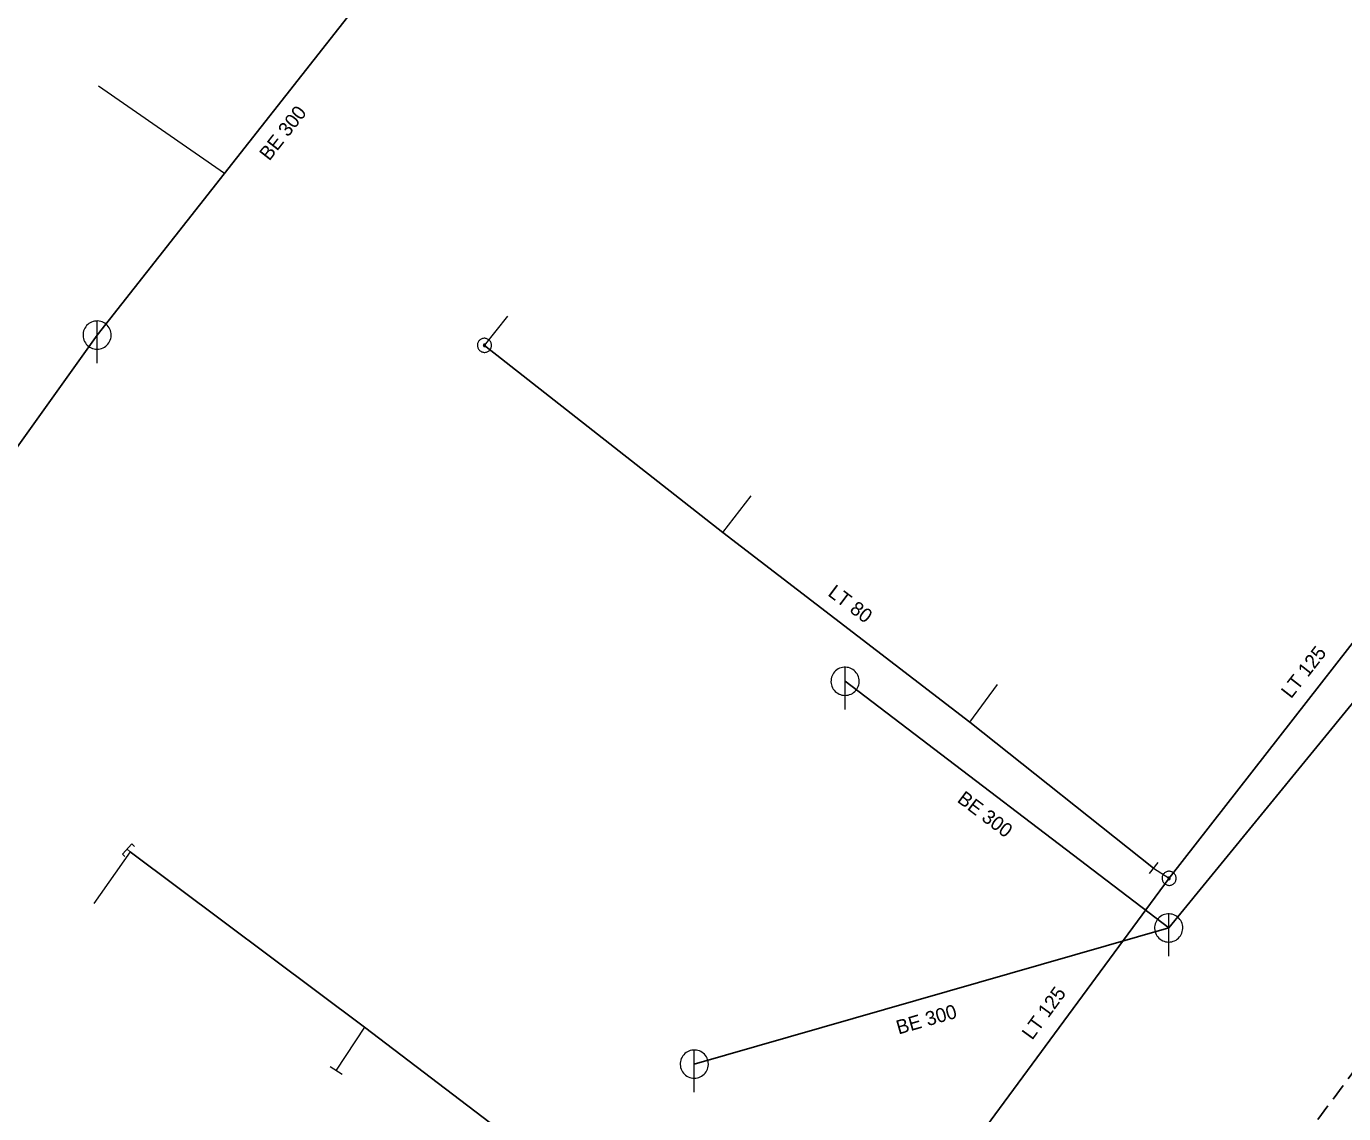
# Model space of a CAD drawing. Extents: x -791337 to -790755, y -988454 to -987923.
# Drawn here: x -790949.7 to -790856.3, y -988339.8 to -988262.8 of the extents above; entities that cross this region are included whole.
import ezdxf

# ---------------------------------------------------------------- set-up
doc = ezdxf.new("R2010")
doc.units = 0
doc.header["$LTSCALE"] = 0.4
doc.linetypes.add('MEDIUM_DASHED', pattern=[4.5, 3, -1.5])
for name, color, linetype, lineweight in [('1', 7, 'Continuous', 13), ('11', 7, 'Continuous', 13), ('13', 7, 'Continuous', 13), ('14', 7, 'Continuous', 25), ('17', 7, 'Continuous', 25), ('22', 7, 'Continuous', 13), ('34', 7, 'Continuous', 13), ('47', 7, 'Continuous', 13), ('63', 7, 'MEDIUM_DASHED', 25)]:
    doc.layers.add(name, color=color, linetype=linetype, lineweight=lineweight)

msp = doc.modelspace()

# ---------------------------------------------------------------- linework, layer by layer
at = {"layer": '11'}
msp.add_line((-790944.59, -988266.969), (-790935.659, -988273.171), dxfattribs=at)
at = {"layer": '13'}
for p, q in [((-790917.221, -988285.369), (-790915.555, -988283.298)), ((-790900.313, -988298.646), (-790898.305, -988296.026)), ((-790882.793, -988312.085), (-790880.839, -988309.421)), ((-790942.351, -988321.278), (-790944.916, -988324.931)), ((-790925.727, -988333.706), (-790927.739, -988336.76))]:
    msp.add_line(p, q, dxfattribs=at)
at = {"layer": '14'}
for p, q in [((-790944.69, -988284.64), (-790919.68, -988252.879)), ((-790902.342, -988336.322), (-790868.702, -988326.671))]:
    msp.add_line(p, q, dxfattribs=at)
at = {"layer": '14', "lineweight": 13}
msp.add_line((-790869.779, -988322.429), (-790868.671, -988323.153), dxfattribs=at)
at = {"layer": '14'}
for points in [[(-790967.359, -988315.936), (-790959.611, -988305.497), (-790944.69, -988284.64)], [(-790891.652, -988309.185), (-790868.702, -988326.671), (-790834.989, -988285.46)]]:
    msp.add_lwpolyline(points, dxfattribs=at)
at = {"layer": '17'}
for points in [[(-790868.671, -988323.153), (-790846.136, -988294.261), (-790834.335, -988278.502)], [(-790917.221, -988285.369), (-790900.313, -988298.646), (-790882.793, -988312.085), (-790869.779, -988322.429)], [(-790942.565, -988321.078), (-790942.351, -988321.278), (-790925.727, -988333.706), (-790908.984, -988346.43), (-790896.409, -988355.739)], [(-790894.383, -988357.266), (-790882.949, -988342.528), (-790868.671, -988323.153)]]:
    msp.add_lwpolyline(points, dxfattribs=at)
at = {"layer": '22'}
for p, q in [((-790944.69, -988286.64), (-790944.689, -988283.64)), ((-790891.652, -988311.185), (-790891.651, -988308.185)), ((-790868.702, -988328.671), (-790868.701, -988325.671)), ((-790902.343, -988338.323), (-790902.342, -988335.323))]:
    msp.add_line(p, q, dxfattribs=at)
for points in [[(-790943.69, -988284.64), (-790943.695, -988284.531), (-790943.713, -988284.423), (-790943.743, -988284.317), (-790943.783, -988284.216), (-790943.835, -988284.119), (-790943.897, -988284.029), (-790943.969, -988283.946), (-790944.049, -988283.872), (-790944.137, -988283.806), (-790944.231, -988283.751), (-790944.331, -988283.706), (-790944.436, -988283.673), (-790944.543, -988283.651), (-790944.652, -988283.641), (-790944.762, -988283.643), (-790944.87, -988283.657), (-790944.977, -988283.682), (-790945.08, -988283.719), (-790945.178, -988283.768), (-790945.27, -988283.826), (-790945.356, -988283.895), (-790945.433, -988283.972), (-790945.502, -988284.058), (-790945.561, -988284.15), (-790945.609, -988284.248), (-790945.646, -988284.351), (-790945.672, -988284.458), (-790945.686, -988284.566), (-790945.689, -988284.676), (-790945.679, -988284.785), (-790945.658, -988284.892), (-790945.624, -988284.996), (-790945.58, -988285.096), (-790945.525, -988285.191), (-790945.459, -988285.279), (-790945.385, -988285.359), (-790945.302, -988285.431), (-790945.212, -988285.493), (-790945.116, -988285.545), (-790945.014, -988285.586), (-790944.909, -988285.616), (-790944.801, -988285.634), (-790944.691, -988285.64), (-790944.582, -988285.634), (-790944.474, -988285.616), (-790944.369, -988285.587), (-790944.267, -988285.546), (-790944.17, -988285.494), (-790944.08, -988285.432), (-790943.997, -988285.361), (-790943.922, -988285.281), (-790943.857, -988285.193), (-790943.801, -988285.099), (-790943.757, -988284.999), (-790943.723, -988284.895), (-790943.701, -988284.787), (-790943.691, -988284.678)], [(-790890.652, -988309.185), (-790890.657, -988309.076), (-790890.675, -988308.968), (-790890.705, -988308.862), (-790890.745, -988308.761), (-790890.797, -988308.664), (-790890.859, -988308.574), (-790890.931, -988308.491), (-790891.011, -988308.417), (-790891.099, -988308.351), (-790891.193, -988308.296), (-790891.293, -988308.251), (-790891.398, -988308.218), (-790891.505, -988308.196), (-790891.614, -988308.186), (-790891.724, -988308.188), (-790891.832, -988308.202), (-790891.939, -988308.227), (-790892.042, -988308.264), (-790892.14, -988308.313), (-790892.232, -988308.371), (-790892.318, -988308.44), (-790892.395, -988308.517), (-790892.464, -988308.603), (-790892.523, -988308.695), (-790892.571, -988308.793), (-790892.608, -988308.896), (-790892.634, -988309.003), (-790892.648, -988309.111), (-790892.651, -988309.221), (-790892.641, -988309.33), (-790892.62, -988309.437), (-790892.586, -988309.541), (-790892.542, -988309.641), (-790892.487, -988309.736), (-790892.421, -988309.824), (-790892.347, -988309.904), (-790892.264, -988309.976), (-790892.174, -988310.038), (-790892.078, -988310.09), (-790891.976, -988310.131), (-790891.871, -988310.161), (-790891.763, -988310.179), (-790891.653, -988310.185), (-790891.544, -988310.179), (-790891.436, -988310.161), (-790891.331, -988310.132), (-790891.229, -988310.091), (-790891.132, -988310.039), (-790891.042, -988309.977), (-790890.959, -988309.906), (-790890.884, -988309.826), (-790890.819, -988309.738), (-790890.763, -988309.644), (-790890.719, -988309.544), (-790890.685, -988309.44), (-790890.663, -988309.332), (-790890.653, -988309.223)], [(-790867.702, -988326.671), (-790867.707, -988326.562), (-790867.725, -988326.454), (-790867.755, -988326.348), (-790867.795, -988326.247), (-790867.847, -988326.15), (-790867.909, -988326.06), (-790867.981, -988325.977), (-790868.061, -988325.903), (-790868.149, -988325.837), (-790868.243, -988325.782), (-790868.343, -988325.737), (-790868.448, -988325.704), (-790868.555, -988325.682), (-790868.664, -988325.672), (-790868.774, -988325.674), (-790868.882, -988325.688), (-790868.989, -988325.713), (-790869.092, -988325.75), (-790869.19, -988325.799), (-790869.282, -988325.857), (-790869.368, -988325.926), (-790869.445, -988326.003), (-790869.514, -988326.089), (-790869.573, -988326.181), (-790869.621, -988326.279), (-790869.658, -988326.382), (-790869.684, -988326.489), (-790869.698, -988326.597), (-790869.701, -988326.707), (-790869.691, -988326.816), (-790869.67, -988326.923), (-790869.636, -988327.027), (-790869.592, -988327.127), (-790869.537, -988327.222), (-790869.471, -988327.31), (-790869.397, -988327.39), (-790869.314, -988327.462), (-790869.224, -988327.524), (-790869.128, -988327.576), (-790869.026, -988327.617), (-790868.921, -988327.647), (-790868.813, -988327.665), (-790868.703, -988327.671), (-790868.594, -988327.665), (-790868.486, -988327.647), (-790868.381, -988327.618), (-790868.279, -988327.577), (-790868.182, -988327.525), (-790868.092, -988327.463), (-790868.009, -988327.392), (-790867.934, -988327.312), (-790867.869, -988327.224), (-790867.813, -988327.13), (-790867.769, -988327.03), (-790867.735, -988326.926), (-790867.713, -988326.818), (-790867.703, -988326.709)], [(-790901.343, -988336.323), (-790901.348, -988336.214), (-790901.366, -988336.106), (-790901.396, -988336), (-790901.436, -988335.899), (-790901.488, -988335.802), (-790901.55, -988335.712), (-790901.622, -988335.629), (-790901.702, -988335.555), (-790901.79, -988335.489), (-790901.884, -988335.434), (-790901.984, -988335.389), (-790902.089, -988335.356), (-790902.196, -988335.334), (-790902.305, -988335.324), (-790902.415, -988335.326), (-790902.523, -988335.34), (-790902.63, -988335.365), (-790902.733, -988335.402), (-790902.831, -988335.451), (-790902.923, -988335.509), (-790903.009, -988335.578), (-790903.086, -988335.655), (-790903.155, -988335.741), (-790903.214, -988335.833), (-790903.262, -988335.931), (-790903.299, -988336.034), (-790903.325, -988336.141), (-790903.339, -988336.249), (-790903.342, -988336.359), (-790903.332, -988336.468), (-790903.311, -988336.575), (-790903.277, -988336.679), (-790903.233, -988336.779), (-790903.178, -988336.874), (-790903.112, -988336.962), (-790903.038, -988337.042), (-790902.955, -988337.114), (-790902.865, -988337.176), (-790902.769, -988337.228), (-790902.667, -988337.269), (-790902.562, -988337.299), (-790902.454, -988337.317), (-790902.344, -988337.323), (-790902.235, -988337.317), (-790902.127, -988337.299), (-790902.022, -988337.27), (-790901.92, -988337.229), (-790901.823, -988337.177), (-790901.733, -988337.115), (-790901.65, -988337.044), (-790901.575, -988336.964), (-790901.51, -988336.876), (-790901.454, -988336.782), (-790901.41, -988336.682), (-790901.376, -988336.578), (-790901.354, -988336.47), (-790901.344, -988336.361)]]:
    msp.add_lwpolyline(points, close=True, dxfattribs=at)
at = {"layer": '34'}
for p, q in [((-790869.467, -988322.037), (-790870.09, -988322.819)), ((-790928.156, -988336.485), (-790927.321, -988337.035))]:
    msp.add_line(p, q, dxfattribs=at)
at = {"layer": '47'}
for points in [[(-790916.827, -988285.677), (-790916.797, -988285.635), (-790916.772, -988285.589), (-790916.752, -988285.541), (-790916.736, -988285.491), (-790916.726, -988285.439), (-790916.721, -988285.387), (-790916.722, -988285.335), (-790916.729, -988285.283), (-790916.74, -988285.232), (-790916.756, -988285.182), (-790916.779, -988285.134), (-790916.806, -988285.09), (-790916.837, -988285.048), (-790916.873, -988285.01), (-790916.912, -988284.975), (-790916.954, -988284.945), (-790917, -988284.92), (-790917.049, -988284.899), (-790917.098, -988284.884), (-790917.15, -988284.874), (-790917.202, -988284.869), (-790917.255, -988284.87), (-790917.307, -988284.876), (-790917.357, -988284.887), (-790917.407, -988284.904), (-790917.455, -988284.927), (-790917.5, -988284.953), (-790917.541, -988284.985), (-790917.579, -988285.021), (-790917.614, -988285.06), (-790917.644, -988285.102), (-790917.669, -988285.148), (-790917.691, -988285.196), (-790917.705, -988285.246), (-790917.715, -988285.298), (-790917.721, -988285.35), (-790917.72, -988285.402), (-790917.714, -988285.454), (-790917.702, -988285.505), (-790917.685, -988285.555), (-790917.662, -988285.603), (-790917.636, -988285.647), (-790917.604, -988285.689), (-790917.568, -988285.727), (-790917.529, -988285.762), (-790917.487, -988285.792), (-790917.441, -988285.817), (-790917.393, -988285.838), (-790917.343, -988285.853), (-790917.291, -988285.863), (-790917.239, -988285.869), (-790917.188, -988285.867), (-790917.136, -988285.861), (-790917.084, -988285.849), (-790917.034, -988285.833), (-790916.986, -988285.81), (-790916.943, -988285.784), (-790916.9, -988285.752), (-790916.862, -988285.716)], [(-790917.156, -988285.419), (-790917.15, -988285.412), (-790917.147, -988285.405), (-790917.144, -988285.397), (-790917.141, -988285.389), (-790917.139, -988285.38), (-790917.139, -988285.372), (-790917.139, -988285.363), (-790917.14, -988285.354), (-790917.142, -988285.346), (-790917.144, -988285.338), (-790917.148, -988285.33), (-790917.153, -988285.323), (-790917.158, -988285.316), (-790917.163, -988285.31), (-790917.17, -988285.304), (-790917.177, -988285.298), (-790917.184, -988285.295), (-790917.192, -988285.292), (-790917.2, -988285.289), (-790917.209, -988285.287), (-790917.217, -988285.287), (-790917.226, -988285.287), (-790917.235, -988285.288), (-790917.244, -988285.289), (-790917.251, -988285.292), (-790917.259, -988285.296), (-790917.266, -988285.301), (-790917.273, -988285.306), (-790917.279, -988285.311), (-790917.285, -988285.318), (-790917.291, -988285.325), (-790917.294, -988285.332), (-790917.297, -988285.34), (-790917.3, -988285.348), (-790917.302, -988285.357), (-790917.303, -988285.365), (-790917.302, -988285.374), (-790917.301, -988285.383), (-790917.3, -988285.392), (-790917.297, -988285.399), (-790917.293, -988285.407), (-790917.288, -988285.414), (-790917.283, -988285.421), (-790917.278, -988285.427), (-790917.271, -988285.433), (-790917.264, -988285.439), (-790917.257, -988285.442), (-790917.249, -988285.445), (-790917.241, -988285.448), (-790917.232, -988285.45), (-790917.224, -988285.451), (-790917.215, -988285.45), (-790917.206, -988285.449), (-790917.198, -988285.447), (-790917.19, -988285.445), (-790917.182, -988285.441), (-790917.175, -988285.436), (-790917.168, -988285.431), (-790917.162, -988285.426)], [(-790868.362, -988322.759), (-790868.405, -988322.729), (-790868.451, -988322.703), (-790868.499, -988322.684), (-790868.548, -988322.668), (-790868.6, -988322.657), (-790868.653, -988322.653), (-790868.704, -988322.654), (-790868.756, -988322.661), (-790868.807, -988322.672), (-790868.857, -988322.689), (-790868.905, -988322.711), (-790868.949, -988322.738), (-790868.991, -988322.769), (-790869.03, -988322.805), (-790869.064, -988322.844), (-790869.094, -988322.887), (-790869.12, -988322.933), (-790869.14, -988322.981), (-790869.155, -988323.03), (-790869.166, -988323.082), (-790869.17, -988323.135), (-790869.169, -988323.187), (-790869.163, -988323.239), (-790869.152, -988323.29), (-790869.134, -988323.339), (-790869.112, -988323.387), (-790869.085, -988323.432), (-790869.054, -988323.473), (-790869.018, -988323.512), (-790868.979, -988323.546), (-790868.936, -988323.576), (-790868.89, -988323.602), (-790868.842, -988323.623), (-790868.793, -988323.637), (-790868.741, -988323.648), (-790868.689, -988323.653), (-790868.636, -988323.652), (-790868.584, -988323.646), (-790868.533, -988323.634), (-790868.484, -988323.616), (-790868.436, -988323.594), (-790868.391, -988323.568), (-790868.35, -988323.536), (-790868.311, -988323.5), (-790868.277, -988323.461), (-790868.247, -988323.418), (-790868.221, -988323.372), (-790868.201, -988323.325), (-790868.186, -988323.275), (-790868.175, -988323.223), (-790868.17, -988323.171), (-790868.172, -988323.119), (-790868.178, -988323.067), (-790868.19, -988323.016), (-790868.207, -988322.966), (-790868.229, -988322.918), (-790868.255, -988322.874), (-790868.287, -988322.832), (-790868.323, -988322.793)], [(-790868.62, -988323.088), (-790868.627, -988323.082), (-790868.635, -988323.079), (-790868.642, -988323.076), (-790868.65, -988323.073), (-790868.659, -988323.071), (-790868.668, -988323.071), (-790868.676, -988323.071), (-790868.685, -988323.072), (-790868.693, -988323.074), (-790868.701, -988323.076), (-790868.709, -988323.08), (-790868.716, -988323.085), (-790868.723, -988323.09), (-790868.729, -988323.095), (-790868.735, -988323.102), (-790868.741, -988323.109), (-790868.744, -988323.117), (-790868.747, -988323.124), (-790868.75, -988323.132), (-790868.752, -988323.141), (-790868.752, -988323.15), (-790868.752, -988323.158), (-790868.751, -988323.167), (-790868.75, -988323.176), (-790868.747, -988323.183), (-790868.743, -988323.191), (-790868.738, -988323.198), (-790868.733, -988323.205), (-790868.728, -988323.211), (-790868.721, -988323.217), (-790868.714, -988323.223), (-790868.706, -988323.226), (-790868.699, -988323.229), (-790868.691, -988323.232), (-790868.682, -988323.234), (-790868.674, -988323.235), (-790868.665, -988323.234), (-790868.656, -988323.233), (-790868.647, -988323.232), (-790868.64, -988323.229), (-790868.632, -988323.225), (-790868.625, -988323.22), (-790868.618, -988323.215), (-790868.612, -988323.21), (-790868.606, -988323.203), (-790868.6, -988323.196), (-790868.597, -988323.188), (-790868.594, -988323.181), (-790868.591, -988323.173), (-790868.589, -988323.164), (-790868.588, -988323.156), (-790868.589, -988323.147), (-790868.59, -988323.138), (-790868.592, -988323.13), (-790868.594, -988323.122), (-790868.598, -988323.114), (-790868.603, -988323.107), (-790868.608, -988323.1), (-790868.613, -988323.094)]]:
    msp.add_lwpolyline(points, close=True, dxfattribs=at)
msp.add_lwpolyline([(-790942.716, -988321.613), (-790942.901, -988321.442), (-790942.228, -988320.713), (-790942.043, -988320.885)], dxfattribs=at)
at = {"layer": '63'}
msp.add_lwpolyline([(-791231.02, -987923.132), (-790755.118, -988202.253), (-790755.118, -988202.253), (-790903.053, -988400.429), (-790903.053, -988400.429), (-791331.504, -988073.857), (-791331.504, -988073.857)], close=True, dxfattribs=at)

# ---------------------------------------------------------------- texts
at = {"layer": '1'}
for s, rotation, p in [('BE 300', 52, (-790932.481, -988272.344)), ('LT 80 ', 323, (-790892.935, -988303.062)), ('LT 125', 52, (-790860.024, -988310.467)), ('BE 300', 323, (-790883.766, -988317.688)), ('LT 125', 54, (-790878.382, -988334.671)), ('BE 300', 16, (-790887.857, -988334.231))]:
    msp.add_text(s, height=1, rotation=rotation, dxfattribs=at).set_placement(p)

doc.saveas('drawing.dxf')
